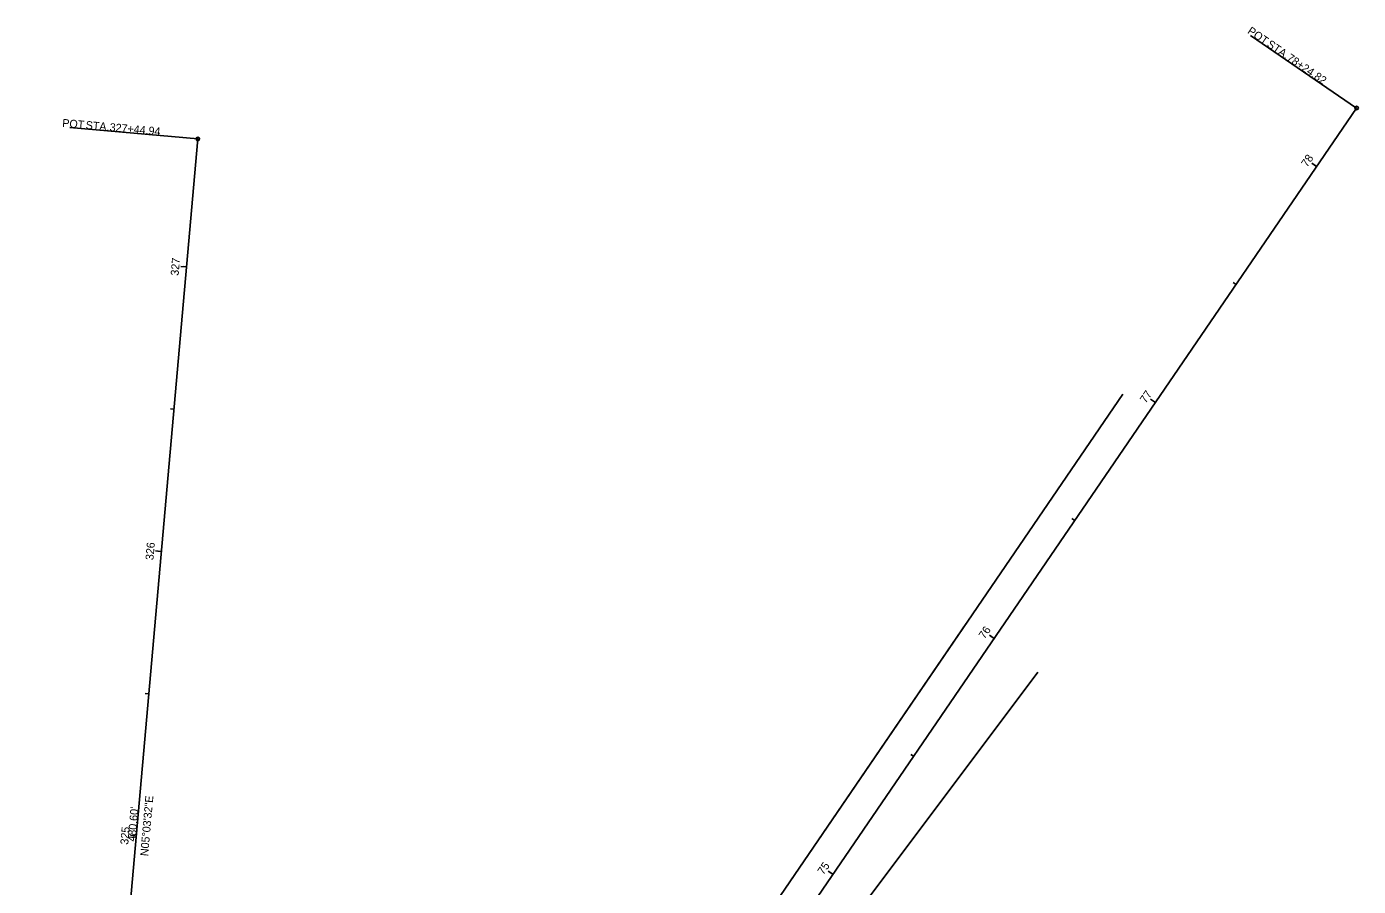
# Model space of a CAD drawing. Extents: x 219353 to 221640, y 361458 to 364236.
# Drawn here: x 220664.5 to 221130.5, y 363935.5 to 364236.4 of the extents above; entities that cross this region are included whole.
import ezdxf

# ---------------------------------------------------------------- set-up
doc = ezdxf.new("R2010")
doc.units = 0
for name, color, linetype in [('DR_P_Cells', 7, 'Continuous'), ('DR_P_GenericNode', 7, 'Continuous'), ('DR_X_Cells', 7, 'Continuous'), ('DT_X_Contour_Major', 7, 'Continuous'), ('DT_X_Contour_Minor', 7, 'Continuous'), ('SC_ProfileRun1', 7, 'Continuous'), ('SC_ProfileRun2', 7, 'Continuous'), ('SC_ProfileRun3', 7, 'Continuous'), ('SC_Scratch1', 7, 'Continuous'), ('SV_X_Break_Lines', 7, 'Continuous'), ('UT_X_Sanitary_Cells', 7, 'Continuous')]:
    doc.layers.add(name, color=color, linetype=linetype)

msp = doc.modelspace()

# ---------------------------------------------------------------- linework, layer by layer
at = {"layer": 'DR_X_Cells'}
for p, q in [((221129.9, 364207.95), (221092.75, 364233.35)), ((220724.41, 364197.12), (220679.58, 364201.09))]:
    msp.add_line(p, q, dxfattribs=at)
for centre in [(221129.9, 364207.95), (220724.41, 364197.12)]:
    msp.add_circle(centre, 0.6, dxfattribs=at)
at = {"layer": 'DT_X_Contour_Major'}
for p, q in [((220664.5, 363526.97), (221129.9, 364207.95)), ((220682.03, 363718.4), (220724.41, 364197.12))]:
    msp.add_line(p, q, dxfattribs=at)
at = {"layer": 'DT_X_Contour_Minor'}
for p, q in [((220772.21, 363704.07), (220993.31, 364027.59)), ((220959, 363931.31), (221018.32, 364010.5))]:
    msp.add_line(p, q, dxfattribs=at)
at = {"layer": 'SC_ProfileRun2'}
for p, q in [((221129.9, 364207.95), (221092.75, 364233.35)), ((220724.41, 364197.12), (220679.58, 364201.09))]:
    msp.add_line(p, q, dxfattribs=at)
for centre in [(221129.9, 364207.95), (220724.41, 364197.12)]:
    msp.add_circle(centre, 0.6, dxfattribs=at)
at = {"layer": 'SC_ProfileRun3'}
for p, q in [((221115.89, 364187.46), (221114.9, 364188.14)), ((220720.44, 364152.35), (220719.25, 364152.46)), ((221059.47, 364104.9), (221058.48, 364105.58)), ((220711.63, 364052.74), (220710.43, 364052.85)), ((221003.04, 364022.34), (221002.05, 364023.02)), ((220702.81, 363953.13), (220700.82, 363953.31)), ((220946.62, 363939.78), (220944.97, 363940.91))]:
    msp.add_line(p, q, dxfattribs=at)
at = {"layer": 'SV_X_Break_Lines'}
msp.add_line((220740.05, 363657.02), (221048.13, 364107.8), dxfattribs=at)
at = {"layer": 'UT_X_Sanitary_Cells'}
for p, q in [((221115.89, 364187.46), (221114.24, 364188.59)), ((220720.44, 364152.35), (220718.45, 364152.53)), ((221087.68, 364146.18), (221086.69, 364146.86)), ((221059.47, 364104.9), (221057.82, 364106.03)), ((220716.03, 364102.55), (220714.84, 364102.65)), ((221031.26, 364063.62), (221030.26, 364064.3)), ((220711.63, 364052.74), (220709.63, 364052.92)), ((221003.04, 364022.34), (221001.39, 364023.47)), ((220707.22, 364002.94), (220706.02, 364003.04)), ((220974.83, 363981.06), (220973.84, 363981.73)), ((220702.81, 363953.13), (220700.82, 363953.31)), ((220946.62, 363939.78), (220944.97, 363940.91))]:
    msp.add_line(p, q, dxfattribs=at)

# ---------------------------------------------------------------- texts
at = {"layer": 'DR_P_Cells'}
msp.add_text("480.60'", height=2.8, rotation=84.9411, dxfattribs=at).set_placement((220702.59, 363951.11))
at = {"layer": 'DR_P_GenericNode'}
msp.add_text("480.60'", height=2.8, rotation=84.9411, dxfattribs=at).set_placement((220702.59, 363951.11))
at = {"layer": 'DR_X_Cells'}
for s, rotation, p in [('POT', 325.6504, (221091.44, 364234.29)), (' STA. ', 325.6504, (221097.38, 364230.23)), ('78+24.82', 325.6504, (221105.18, 364224.89)), ('POT', 354.9411, (220676.87, 364201.37)), (' STA. ', 354.9411, (220684.04, 364200.73)), ('327+44.94', 354.9411, (220693.46, 364199.9))]:
    msp.add_text(s, height=2.8, rotation=rotation, dxfattribs=at).set_placement(p)
at = {"layer": 'SC_ProfileRun1'}
msp.add_text('N05°03\'32"E', height=2.8, rotation=84.9411, dxfattribs=at).set_placement((220707, 363946.02))
at = {"layer": 'SC_ProfileRun2'}
for s, rotation, p in [('POT', 325.6504, (221091.44, 364234.29)), (' STA. ', 325.6504, (221097.38, 364230.23)), ('78+24.82', 325.6504, (221105.18, 364224.89)), ('POT', 354.9411, (220676.87, 364201.37)), (' STA. ', 354.9411, (220684.04, 364200.73)), ('327+44.94', 354.9411, (220693.46, 364199.9))]:
    msp.add_text(s, height=2.8, rotation=rotation, dxfattribs=at).set_placement(p)
at = {"layer": 'SC_ProfileRun3'}
for s, rotation, p in [('325', 84.9411, (220700.03, 363950.06)), ('75', 55.6504, (220943.32, 363939.38))]:
    msp.add_text(s, height=2.8, rotation=rotation, dxfattribs=at).set_placement(p)
at = {"layer": 'SC_Scratch1'}
msp.add_text('N05°03\'32"E', height=2.8, rotation=84.9411, dxfattribs=at).set_placement((220707, 363946.02))
at = {"layer": 'UT_X_Sanitary_Cells'}
for s, rotation, p in [('78', 55.6504, (221112.58, 364187.04)), ('327', 84.9411, (220717.65, 364149.17)), ('77', 55.6504, (221056.11, 364104.41)), ('326', 84.9411, (220708.84, 364049.62)), ('76', 55.6504, (220999.71, 364021.9)), ('325', 84.9411, (220700.03, 363950.06)), ('75', 55.6504, (220943.32, 363939.38))]:
    msp.add_text(s, height=2.8, rotation=rotation, dxfattribs=at).set_placement(p)

doc.saveas('drawing.dxf')
